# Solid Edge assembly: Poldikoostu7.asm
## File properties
Author: Türk
Template: Iso Assembly.asm
Last saved by: Türk
Revision: 3
Application: Solid Edge
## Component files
Polt220x20.par
Mutter.par
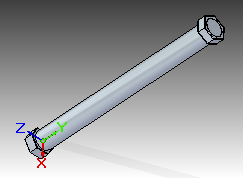
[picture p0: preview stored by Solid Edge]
